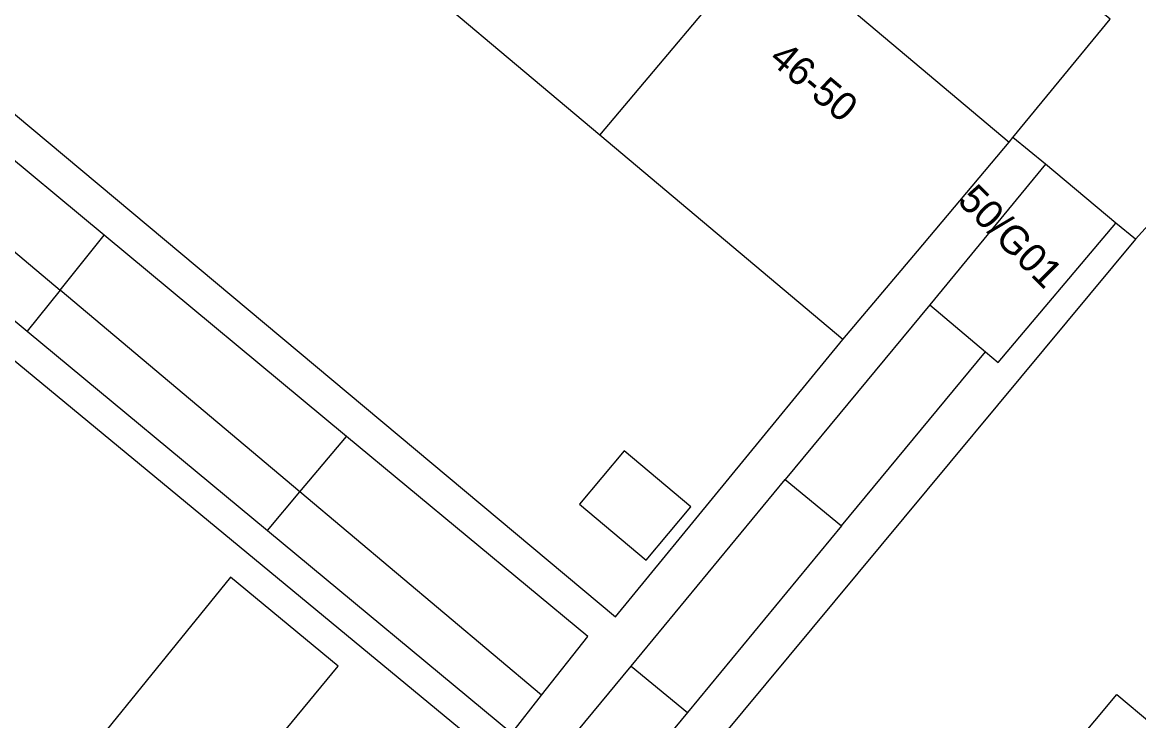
# Model space of a CAD drawing. Extents: x 162074 to 163034, y 381824 to 382557.
# Drawn here: x 162449.04 to 162488.23, y 382096.24 to 382120.75 of the extents above; entities that cross this region are included whole.
import ezdxf

# ---------------------------------------------------------------- set-up
doc = ezdxf.new("R2010")
doc.units = 0
for name, color, linetype in [('IMGEO_Pand', 7, 'Continuous'), ('IMGEO_Pand_nummerreeks', 7, 'Continuous'), ('IMGEO_Voetpad_open', 7, 'Continuous')]:
    doc.layers.add(name, color=color, linetype=linetype)

msp = doc.modelspace()

# ---------------------------------------------------------------- linework, layer by layer
at = {"layer": 'IMGEO_Pand'}
for points in [[(162469.315, 382116.792), (162460.898, 382123.872)], [(162469.315, 382116.792), (162475.149, 382123.727)], [(162475.149, 382123.727), (162483.68, 382116.552)], [(162451.913, 382113.279), (162443.449, 382120.301)], [(162441.948, 382118.43), (162450.366, 382111.349)], [(162440.745, 382116.93), (162449.209, 382109.908)], [(162477.847, 382109.617), (162469.315, 382116.792)], [(162477.847, 382109.617), (162480.462, 382112.726), (162483.68, 382116.552)], [(162484.954, 382115.781), (162480.89, 382110.834)], [(162487.42, 382113.707), (162484.954, 382115.781)], [(162482.851, 382109.185), (162483.299, 382108.808), (162487.42, 382113.707)], [(162450.366, 382111.349), (162451.913, 382113.279)], [(162460.422, 382106.219), (162451.913, 382113.279)], [(162450.366, 382111.349), (162449.209, 382109.908)], [(162458.782, 382104.27), (162450.366, 382111.349)], [(162480.89, 382110.834), (162475.815, 382104.704)], [(162480.89, 382110.834), (162482.851, 382109.185)], [(162449.209, 382109.908), (162457.641, 382102.913)], [(162477.794, 382103.076), (162482.851, 382109.185)], [(162458.782, 382104.27), (162460.422, 382106.219)], [(162467.266, 382097.134), (162468.886, 382099.197), (162460.422, 382106.219)], [(162470.169, 382105.709), (162468.598, 382103.842), (162470.936, 382101.875), (162472.507, 382103.742), (162470.169, 382105.709)], [(162470.406, 382098.153), (162475.815, 382104.704)], [(162475.815, 382104.704), (162477.794, 382103.076)], [(162457.641, 382102.913), (162458.782, 382104.27)], [(162467.266, 382097.134), (162458.782, 382104.27)], [(162477.794, 382103.076), (162472.384, 382096.524)], [(162457.641, 382102.913), (162466.216, 382095.799), (162467.266, 382097.134)], [(162457.546, 382084.897), (162457.449, 382084.977), (162458.753, 382086.556), (162453.876, 382090.581), (162460.128, 382098.157), (162456.35, 382101.275), (162448.864, 382092.063)], [(162483.743, 382090.108), (162485.653, 382092.386), (162484.368, 382093.463), (162487.463, 382097.156), (162488.689, 382096.129), (162490.761, 382098.6)], [(162465.311, 382091.983), (162470.406, 382098.153)], [(162470.406, 382098.153), (162472.384, 382096.524)], [(162472.384, 382096.524), (162467.289, 382090.354)]]:
    msp.add_lwpolyline(points, dxfattribs=at)
at = {"layer": 'IMGEO_Voetpad_open'}
for points in [[(162483.81, 382116.71), (162487.224, 382120.866), (162419.203, 382177.117)], [(162389.437, 382141.114), (162397.649, 382151.094), (162465.734, 382094.868), (162457.546, 382084.897)], [(162410.672, 382149.403), (162469.86, 382099.891), (162477.847, 382109.617)], [(162483.68, 382116.552), (162483.81, 382116.71)], [(162484.954, 382115.781), (162483.81, 382116.71)], [(162498.079, 382106.838), (162489.12, 382114.253), (162488.112, 382113.139)], [(162488.112, 382113.139), (162487.42, 382113.707)], [(162488.112, 382113.139), (162454.033, 382072.15), (162453.74, 382071.792), (162453.561, 382071.549)]]:
    msp.add_lwpolyline(points, dxfattribs=at)

# ---------------------------------------------------------------- texts
at = {"layer": 'IMGEO_Pand_nummerreeks'}
for s, rotation, p in [('46-50', 319.9359, (162475.204, 382119.394)), ('50/G01', 314.9999, (162481.829, 382114.45))]:
    msp.add_text(s, height=1, rotation=rotation, dxfattribs=at).set_placement(p)

doc.saveas('drawing.dxf')
